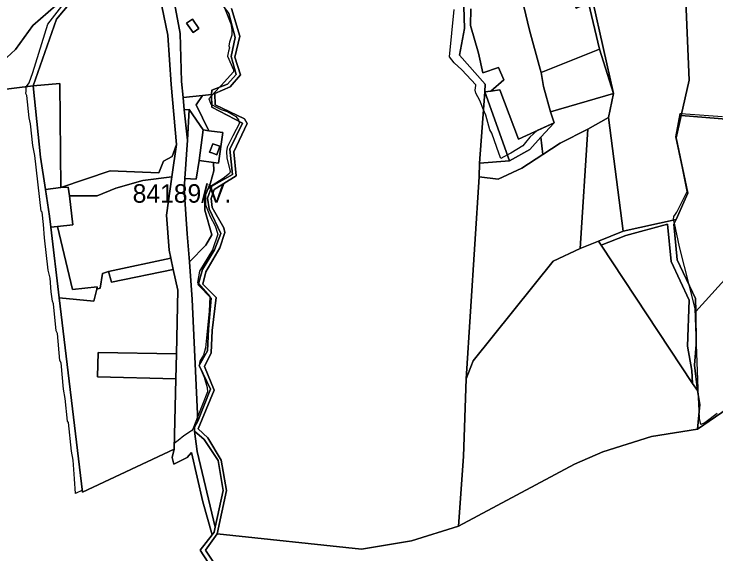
# Model space of a CAD drawing. Extents: x -477304 to -465429, y -1159113 to -1149210.
# Drawn here: x -473001 to -472430, y -1154555 to -1154116 of the extents above; entities that cross this region are included whole.
import ezdxf

# ---------------------------------------------------------------- set-up
doc = ezdxf.new("R2010")
doc.units = 0
for name, color, linetype in [('BPEJ_s', 7, 'Continuous'), ('ostatni_s', 7, 'Continuous'), ('PUPFL_s', 7, 'Continuous'), ('trav_porost_s', 7, 'Continuous'), ('voda_s', 7, 'Continuous')]:
    doc.layers.add(name, color=color, linetype=linetype)

msp = doc.modelspace()

# ---------------------------------------------------------------- linework, layer by layer
at = {"layer": 'BPEJ_s'}
for points in [[(-472987.65, -1154205.34), (-472988.93, -1154200.66), (-472990.63, -1154182.37), (-472991.48, -1154180.88), (-472991.4, -1154178.87), (-472991.26, -1154175.57), (-472991.11, -1154175.34), (-472991.05, -1154175.25), (-472988.93, -1154172.16), (-472985.95, -1154163.66), (-472973.62, -1154124.53), (-472956.73, -1154102.22)], [(-472991.48, -1154180.88), (-472991.4, -1154178.87), (-472991.26, -1154175.57), (-472991.11, -1154175.34), (-472991.05, -1154175.25), (-472988.93, -1154172.16), (-472985.95, -1154163.66), (-472973.62, -1154124.53), (-472956.73, -1154102.22)], [(-472530.52, -1154106.09), (-472513.63, -1154180.72), (-472525.05, -1154144.76), (-472572.62, -1154163.71), (-472570.69, -1154175.01), (-472564.9, -1154195.68), (-472562.1, -1154204.59), (-472575.93, -1154210.94), (-472581.73, -1154216.39), (-472585.21, -1154220.65), (-472587.46, -1154223.41), (-472597.25, -1154229.15), (-472600, -1154230.66), (-472605.31, -1154233.57), (-472606.6, -1154230), (-472612.77, -1154212.99), (-472614.26, -1154210.44), (-472617.66, -1154198.53), (-472619.46, -1154194.14), (-472622.55, -1154186.62), (-472625.74, -1154180.67), (-472626.17, -1154178.12), (-472625.78, -1154174.24), (-472625.74, -1154173.87), (-472637.01, -1154161.53), (-472643.39, -1154156), (-472647.22, -1154150.9), (-472643.18, -1154112.63)], [(-472530.52, -1154106.09), (-472513.63, -1154180.72), (-472525.05, -1154144.76), (-472572.62, -1154163.71), (-472570.69, -1154175.01), (-472564.9, -1154195.68), (-472562.1, -1154204.59), (-472575.93, -1154210.94), (-472581.73, -1154216.39), (-472585.21, -1154220.65), (-472587.46, -1154223.41), (-472597.25, -1154229.15), (-472600, -1154230.66), (-472605.31, -1154233.57), (-472606.6, -1154230), (-472612.77, -1154212.99), (-472614.26, -1154210.44), (-472617.66, -1154198.53), (-472619.46, -1154194.14), (-472622.55, -1154186.62), (-472625.74, -1154180.67), (-472626.17, -1154178.12), (-472625.78, -1154174.24), (-472625.74, -1154173.87), (-472637.01, -1154161.53), (-472643.39, -1154156), (-472647.22, -1154150.9), (-472643.18, -1154112.63)], [(-472829.93, -1154111.14), (-472824.98, -1154124.11), (-472824.13, -1154129.21), (-472824.13, -1154133.46), (-472826.05, -1154139.21), (-472826.47, -1154141.97), (-472826.05, -1154143.67), (-472826.67, -1154146.52), (-472827.53, -1154150.48), (-472822.64, -1154161.53), (-472822.64, -1154163.23), (-472832.85, -1154174.29), (-472834.08, -1154175.62), (-472840.6, -1154182.69), (-472842.8, -1154185.07), (-472841.14, -1154189.39), (-472840.48, -1154189.75), (-472836.49, -1154191.89), (-472832.85, -1154193.85), (-472827.75, -1154195.55), (-472820.94, -1154199.59), (-472818.6, -1154202.15), (-472818.31, -1154203.43), (-472818.18, -1154203.99), (-472817.96, -1154204.91), (-472823.14, -1154215.26), (-472827.75, -1154224.47), (-472828.39, -1154227.88), (-472828.17, -1154232.98), (-472825.41, -1154244.04), (-472826.05, -1154245.74), (-472831.15, -1154249.99), (-472842.21, -1154256.79), (-472843.39, -1154258.15), (-472843.69, -1154258.5), (-472844.61, -1154261.02), (-472845.4, -1154263.17), (-472845.61, -1154271.25), (-472841.78, -1154280.61), (-472837.53, -1154288.26), (-472835.4, -1154295.07), (-472839.87, -1154307.83), (-472850.5, -1154325.05), (-472852.1, -1154334.31), (-472851.6, -1154334.86), (-472851.27, -1154335.23), (-472841.99, -1154345.68), (-472842, -1154345.86), (-472842.42, -1154357.58), (-472845.4, -1154387.35), (-472847.1, -1154393.31), (-472848.39, -1154395.44), (-472850.07, -1154398.2), (-472850.71, -1154401.81), (-472846.46, -1154411.17), (-472844.12, -1154419.67), (-472843.91, -1154423.08), (-472851.96, -1154443.63), (-472855.82, -1154453.48), (-472856.88, -1154454.97), (-472863.05, -1154459.01), (-472867.79, -1154462.74), (-472870.94, -1154465.22), (-472871.05, -1154469.78), (-472945.41, -1154504.69), (-472945.61, -1154503.04), (-472951.09, -1154505.74), (-472951.93, -1154493.89), (-472952.99, -1154478.79), (-472954.48, -1154471.35), (-472956.82, -1154448.17), (-472957.67, -1154446.89), (-472959.58, -1154428.61), (-472961.07, -1154420.95), (-472962.98, -1154399.69), (-472963.83, -1154397.77), (-472965.96, -1154375.87), (-472966.81, -1154373.53), (-472969.15, -1154351.63), (-472970, -1154349.5), (-472971.07, -1154341.85), (-472971.92, -1154330.79), (-472973.4, -1154324.41), (-472976.28, -1154298.04), (-472977.34, -1154287.13), (-472978.3, -1154277.21), (-472978.93, -1154276.57), (-472979.14, -1154276.36), (-472984.25, -1154231.28), (-472985.95, -1154222.98), (-472987.65, -1154205.34), (-472988.93, -1154200.66), (-472990.63, -1154182.37), (-472991.48, -1154180.88)], [(-472829.93, -1154111.14), (-472824.98, -1154124.11), (-472824.13, -1154129.21), (-472824.13, -1154133.46), (-472826.05, -1154139.21), (-472826.47, -1154141.97), (-472826.05, -1154143.67), (-472826.67, -1154146.52), (-472827.53, -1154150.48), (-472822.64, -1154161.53), (-472822.64, -1154163.23), (-472832.85, -1154174.29), (-472834.08, -1154175.62), (-472840.6, -1154182.69), (-472842.8, -1154185.07), (-472841.14, -1154189.39), (-472840.48, -1154189.75), (-472836.49, -1154191.89), (-472832.85, -1154193.85), (-472827.75, -1154195.55), (-472820.94, -1154199.59), (-472818.6, -1154202.15), (-472818.31, -1154203.43), (-472818.18, -1154203.99), (-472817.96, -1154204.91), (-472823.14, -1154215.26), (-472827.75, -1154224.47), (-472828.39, -1154227.88), (-472828.17, -1154232.98), (-472825.41, -1154244.04), (-472826.05, -1154245.74), (-472831.15, -1154249.99), (-472842.21, -1154256.79), (-472843.39, -1154258.15), (-472843.69, -1154258.5), (-472844.61, -1154261.02), (-472845.4, -1154263.17), (-472845.61, -1154271.25), (-472841.78, -1154280.61), (-472837.53, -1154288.26), (-472835.4, -1154295.07), (-472839.87, -1154307.83), (-472850.5, -1154325.05), (-472852.1, -1154334.31), (-472851.6, -1154334.86), (-472851.27, -1154335.23), (-472841.99, -1154345.68), (-472842, -1154345.86), (-472842.42, -1154357.58), (-472845.4, -1154387.35), (-472847.1, -1154393.31), (-472848.39, -1154395.44), (-472850.07, -1154398.2), (-472850.71, -1154401.81), (-472846.46, -1154411.17), (-472844.12, -1154419.67), (-472843.91, -1154423.08), (-472851.96, -1154443.63), (-472855.82, -1154453.48), (-472856.88, -1154454.97), (-472863.05, -1154459.01), (-472867.79, -1154462.74), (-472870.94, -1154465.22), (-472871.05, -1154469.78), (-472945.41, -1154504.69), (-472945.61, -1154503.04), (-472951.09, -1154505.74), (-472951.93, -1154493.89), (-472952.99, -1154478.79), (-472954.48, -1154471.35), (-472956.82, -1154448.17), (-472957.67, -1154446.89), (-472959.58, -1154428.61), (-472961.07, -1154420.95), (-472962.98, -1154399.69), (-472963.83, -1154397.77), (-472965.96, -1154375.87), (-472966.81, -1154373.53), (-472969.15, -1154351.63), (-472970, -1154349.5), (-472971.07, -1154341.85), (-472971.92, -1154330.79), (-472973.4, -1154324.41), (-472976.28, -1154298.04), (-472977.34, -1154287.13), (-472978.3, -1154277.21), (-472978.93, -1154276.57), (-472979.14, -1154276.36), (-472984.25, -1154231.28), (-472985.95, -1154222.98), (-472987.65, -1154205.34)], [(-472429.42, -1154440.69), (-472439.62, -1154448.34), (-472442.81, -1154449.83), (-472443.87, -1154444.73), (-472444.11, -1154438.57), (-472444.52, -1154427.69), (-472446.71, -1154370.27), (-472447.27, -1154355.49), (-472451.91, -1154337.24), (-472460.02, -1154305.35), (-472464.25, -1154286.23), (-472464.85, -1154283.52), (-472464.91, -1154283.25), (-472464.69, -1154280.7), (-472463.36, -1154278.76), (-472462.36, -1154277.3), (-472453.86, -1154260.3), (-472457.75, -1154241.45), (-472462.99, -1154216.1), (-472459.67, -1154197.08), (-472458.48, -1154197.17), (-472455.13, -1154197.41), (-472425.17, -1154199.53)], [(-472462.99, -1154216.1), (-472459.67, -1154197.08), (-472458.48, -1154197.17), (-472455.13, -1154197.41), (-472425.17, -1154199.53)], [(-472429.42, -1154440.69), (-472439.62, -1154448.34), (-472442.81, -1154449.83), (-472443.87, -1154444.73), (-472444.11, -1154438.57), (-472444.52, -1154427.69), (-472446.71, -1154370.27), (-472447.27, -1154355.49), (-472451.91, -1154337.24), (-472460.02, -1154305.35), (-472464.25, -1154286.23), (-472464.85, -1154283.52), (-472464.91, -1154283.25), (-472464.69, -1154280.7), (-472463.36, -1154278.76), (-472462.36, -1154277.3), (-472453.86, -1154260.3), (-472457.75, -1154241.45), (-472462.99, -1154216.1)]]:
    msp.add_lwpolyline(points, dxfattribs=at)
at = {"layer": 'ostatni_s'}
for points in [[(-472849.47, -1154085.86), (-472826.39, -1154115.72), (-472821.44, -1154135.2), (-472824.75, -1154150.78), (-472820.69, -1154165.29), (-472827.68, -1154173.11), (-472840.4, -1154178.1), (-472840.62, -1154181.74), (-472847.97, -1154182.52), (-472863.75, -1154184.19), (-472865.04, -1154171.03), (-472866.09, -1154132.18), (-472873.67, -1154091.14), (-472874.54, -1154081.71), (-472850.45, -1154078.85)], [(-472860.87, -1154123.6), (-472856.13, -1154120.35), (-472850.9, -1154128.03), (-472855.64, -1154131.28)], [(-472860.87, -1154123.6), (-472855.64, -1154131.28), (-472850.9, -1154128.03), (-472856.13, -1154120.35)], [(-472979.68, -1154232.42), (-472985.59, -1154174.56), (-472964.05, -1154172.75), (-472963.19, -1154257.3), (-472975.68, -1154258.78)], [(-472842.76, -1154211.06), (-472847.39, -1154210.45), (-472858.83, -1154193.67), (-472862.79, -1154194.03), (-472863.75, -1154184.19), (-472847.97, -1154182.52), (-472853.07, -1154189.9)], [(-472838.2, -1154307.72), (-472847.95, -1154323.76), (-472851.53, -1154336.12), (-472840.79, -1154347.1), (-472843.18, -1154372.38), (-472843.81, -1154389.75), (-472850.55, -1154401.76), (-472841.36, -1154421.1), (-472851.81, -1154446.9), (-472856.2, -1154348.26), (-472858.61, -1154317.62), (-472845.2, -1154304.01), (-472840.29, -1154295.5), (-472846.14, -1154275.51), (-472845.97, -1154264.61), (-472841.48, -1154253.36), (-472838.81, -1154243.57), (-472839.1, -1154236.76), (-472834.84, -1154237.32), (-472831.53, -1154212.54), (-472842.76, -1154211.06), (-472853.07, -1154189.9), (-472847.97, -1154182.52), (-472840.62, -1154181.74), (-472840.44, -1154191.97), (-472815.32, -1154204.98), (-472825.67, -1154226.16), (-472823.67, -1154246.68), (-472840.44, -1154256.02), (-472843.81, -1154265.84), (-472842.41, -1154274.41), (-472833.08, -1154294.59)], [(-472862.79, -1154194.03), (-472858.83, -1154193.67), (-472860.13, -1154218.63)], [(-472847.39, -1154210.45), (-472850.7, -1154235.23), (-472853.06, -1154250.42), (-472862.35, -1154249.95), (-472860.13, -1154218.63), (-472858.83, -1154193.67)], [(-472839.1, -1154236.76), (-472850.7, -1154235.23), (-472847.39, -1154210.45), (-472842.76, -1154211.06), (-472831.53, -1154212.54), (-472834.84, -1154237.32)], [(-472841.4, -1154226.45), (-472839.66, -1154221.58), (-472833.9, -1154223.64), (-472836.36, -1154230.52), (-472839.55, -1154229.38), (-472842.12, -1154228.46)], [(-472839.55, -1154229.38), (-472836.36, -1154230.52), (-472833.9, -1154223.64), (-472839.66, -1154221.58), (-472841.4, -1154226.45), (-472842.12, -1154228.46)], [(-472862.35, -1154249.95), (-472853.06, -1154250.42), (-472850.7, -1154235.23), (-472839.1, -1154236.76), (-472838.81, -1154243.57), (-472841.48, -1154253.36), (-472845.97, -1154264.61), (-472846.14, -1154275.51), (-472840.29, -1154295.5), (-472845.2, -1154304.01), (-472858.61, -1154317.62), (-472860.41, -1154294.73), (-472862.93, -1154258.74)], [(-472953.65, -1154340), (-472933.45, -1154337.95), (-472933.87, -1154339.66), (-472936.3, -1154349.56), (-472964.39, -1154346.9), (-472971.3, -1154289.5), (-472965.81, -1154288.88)], [(-472924.26, -1154325.38), (-472873.71, -1154314.49), (-472871.67, -1154323.79), (-472921.9, -1154334.14)], [(-472932.86, -1154391.11), (-472869.16, -1154392.27), (-472869.66, -1154412.62), (-472933.18, -1154410.97)], [(-472852.18, -1154471.56), (-472854.38, -1154455.06), (-472846.45, -1154462), (-472835.17, -1154478.9), (-472831.05, -1154503.44), (-472837.52, -1154533.23)]]:
    msp.add_lwpolyline(points, close=True, dxfattribs=at)
msp.add_lwpolyline([(-472873.67, -1154091.14), (-472866.09, -1154132.18), (-472865.04, -1154171.03), (-472863.75, -1154184.19), (-472862.79, -1154194.03), (-472860.13, -1154218.63), (-472862.35, -1154249.95), (-472862.93, -1154258.74), (-472860.41, -1154294.73), (-472858.61, -1154317.62), (-472856.2, -1154348.26), (-472851.81, -1154446.9), (-472854.54, -1154451.8), (-472854.38, -1154455.06), (-472852.18, -1154471.56), (-472837.52, -1154533.23), (-472838.38, -1154537.19), (-472840.12, -1154539.39), (-472847.77, -1154512.55), (-472856.9, -1154472.41), (-472860.49, -1154476.63), (-472871.2, -1154481.8), (-472872.59, -1154476.5), (-472871.05, -1154469.78), (-472869.66, -1154412.62), (-472869.16, -1154392.27), (-472867.91, -1154340.66), (-472871.67, -1154323.79), (-472873.71, -1154314.49), (-472874.92, -1154308.19), (-472877.2, -1154279.68), (-472872.82, -1154248.6), (-472869.12, -1154222.34), (-472873.31, -1154173.48), (-472876.21, -1154133.46), (-472885.88, -1154086.14)], dxfattribs=at)
at = {"layer": 'PUPFL_s'}
for points in [[(-472458.42, -1153888.26), (-472456.78, -1153884.15), (-472439.98, -1153867.43), (-472437.22, -1153927.39), (-472440.92, -1153982.01), (-472446.75, -1154005.15), (-472458.38, -1154050.48), (-472455.38, -1154092.67), (-472452.22, -1154169.89), (-472458.83, -1154198.7), (-472462.78, -1154216.95), (-472453.33, -1154261.75), (-472462.8, -1154283.06), (-472506.01, -1154292.72), (-472517.7, -1154200.33), (-472513.63, -1154180.72), (-472530.52, -1154106.09), (-472468.28, -1154095.1), (-472465.12, -1154094.54), (-472465.12, -1154053.36), (-472458.54, -1153980.69)], [(-472394.38, -1154075.28), (-472401.16, -1154143.14), (-472408.66, -1154202.61), (-472458.83, -1154198.7), (-472452.22, -1154169.89), (-472455.38, -1154092.67)], [(-472939.6, -1154087.83), (-472966.52, -1154120.43), (-472985.59, -1154174.56), (-473014.5, -1154178.21), (-473015.58, -1154176.17), (-473017.49, -1154164.82), (-473010.66, -1154154.9), (-472999.88, -1154145.17), (-472985.98, -1154125.69), (-472967.29, -1154109.37), (-472954.27, -1154100.56), (-472943.73, -1154089.62), (-472939.03, -1154083), (-472934.33, -1154083.49)], [(-472570.69, -1154175.01), (-472572.62, -1154163.71), (-472525.05, -1154144.76), (-472513.63, -1154180.72), (-472564.9, -1154195.68)], [(-472598.3, -1154235.42), (-472622.78, -1154237.39), (-472618.34, -1154179.49)], [(-472618.34, -1154179.49), (-472613.45, -1154178.87), (-472606.1, -1154177.93), (-472591.09, -1154217.9), (-472562.1, -1154204.59), (-472572.95, -1154216.31), (-472581.78, -1154226.42), (-472598.3, -1154235.42)], [(-472571.18, -1154230.49), (-472572.95, -1154216.31), (-472562.1, -1154204.59), (-472564.9, -1154195.68), (-472513.63, -1154180.72), (-472517.7, -1154200.33), (-472534.54, -1154209.69), (-472557.09, -1154221.24)], [(-472453.33, -1154261.75), (-472462.78, -1154216.95), (-472458.83, -1154198.7), (-472408.66, -1154202.61), (-472420.83, -1154329.2), (-472446.86, -1154358.02), (-472447.19, -1154347.21), (-472462.02, -1154315.9), (-472464.6, -1154287), (-472462.8, -1154283.06)], [(-472534.54, -1154209.69), (-472517.7, -1154200.33), (-472506.01, -1154292.72), (-472525.94, -1154300.77), (-472540.75, -1154306.65)], [(-472588.19, -1154241.54), (-472571.18, -1154230.49), (-472557.09, -1154221.24), (-472534.54, -1154209.69), (-472540.75, -1154306.65), (-472562.68, -1154317.09), (-472627.92, -1154398.05), (-472633.5, -1154412.68), (-472623.07, -1154248.49), (-472607.42, -1154250.34)], [(-472598.3, -1154235.42), (-472581.78, -1154226.42), (-472572.95, -1154216.31), (-472571.18, -1154230.49), (-472588.19, -1154241.54), (-472607.42, -1154250.34), (-472623.07, -1154248.49), (-472622.78, -1154237.39)], [(-472953.28, -1154287.48), (-472965.81, -1154288.88), (-472971.3, -1154289.5), (-472972.38, -1154280.5), (-472975.68, -1154258.78), (-472963.19, -1154257.3), (-472957.17, -1154256.98), (-472956.15, -1154263.81)], [(-472445.38, -1154422.01), (-472447.92, -1154401.59), (-472446.53, -1154384.74), (-472446.86, -1154358.02), (-472420.83, -1154329.2), (-472360.26, -1154262.14), (-472384.09, -1154410.55), (-472401.42, -1154423.45), (-472445.42, -1154453.37), (-472443.65, -1154433.44)], [(-472445.38, -1154422.01), (-472449.51, -1154416.38), (-472449.98, -1154405.9), (-472453.63, -1154386.05), (-472452.36, -1154348.77), (-472466.94, -1154317.29), (-472469.9, -1154286.92), (-472503.75, -1154296.21), (-472523.88, -1154304.06), (-472525.94, -1154300.77), (-472506.01, -1154292.72), (-472462.8, -1154283.06), (-472464.6, -1154287), (-472462.02, -1154315.9), (-472447.19, -1154347.21), (-472446.86, -1154358.02), (-472446.53, -1154384.74), (-472447.92, -1154401.59)], [(-472469.9, -1154286.92), (-472466.94, -1154317.29), (-472452.36, -1154348.77), (-472453.63, -1154386.05), (-472449.98, -1154405.9), (-472449.51, -1154416.38), (-472523.88, -1154304.06), (-472503.75, -1154296.21)], [(-472525.94, -1154300.77), (-472523.88, -1154304.06), (-472449.51, -1154416.38), (-472445.38, -1154422.01), (-472443.65, -1154433.44), (-472445.42, -1154453.37), (-472482.74, -1154459.45), (-472522.51, -1154471.95), (-472545.51, -1154481.81), (-472639.66, -1154532.36), (-472635.69, -1154475.83), (-472633.5, -1154412.68), (-472627.92, -1154398.05), (-472562.68, -1154317.09), (-472540.75, -1154306.65)]]:
    msp.add_lwpolyline(points, close=True, dxfattribs=at)
for points in [[(-473028.58, -1154013.8), (-472995.53, -1153992.99), (-472988.79, -1153987.76), (-472984.49, -1154008.11), (-472964.26, -1154022.87), (-472935.97, -1154028.45), (-472913.88, -1154035), (-472888.58, -1154036.61), (-472885.69, -1154043.9), (-472884.83, -1154050.9), (-472898.18, -1154053.7), (-472922.79, -1154060.6), (-472939.03, -1154083), (-472943.73, -1154089.62), (-472954.27, -1154100.56), (-472967.29, -1154109.37), (-472985.98, -1154125.69), (-472999.88, -1154145.17), (-473010.66, -1154154.9)], [(-472635.34, -1154110.22), (-472635.02, -1154127.99), (-472638.86, -1154149.74), (-472618.01, -1154173.32), (-472618.34, -1154179.49), (-472622.78, -1154237.39), (-472623.07, -1154248.49), (-472633.5, -1154412.68), (-472635.69, -1154475.83), (-472639.66, -1154532.36), (-472678.01, -1154544.18), (-472718.68, -1154550.96), (-472836.02, -1154538.48), (-472828.3, -1154503.34), (-472832.72, -1154478.74), (-472843.67, -1154460.59), (-472851.46, -1154453.29), (-472838.41, -1154421.8), (-472846.27, -1154402.6), (-472840.76, -1154391.42), (-472840.13, -1154373.22), (-472836.79, -1154346.46), (-472847.74, -1154335.73), (-472845.21, -1154325.68), (-472833.81, -1154306.11), (-472829.81, -1154293.73), (-472830.58, -1154290.05), (-472840.13, -1154273.36), (-472840.79, -1154266.21), (-472838.34, -1154258.74), (-472820.51, -1154247.63), (-472822.37, -1154228.2), (-472811.6, -1154205.15), (-472813.85, -1154201.26), (-472837.5, -1154189.94), (-472837.81, -1154180.81), (-472825.5, -1154175.49), (-472817.11, -1154165.54), (-472821.53, -1154151.22), (-472817.57, -1154134.23), (-472824.3, -1154111.78)], [(-473014.5, -1154178.21), (-472985.59, -1154174.56), (-472979.68, -1154232.42), (-472975.68, -1154258.78), (-472972.38, -1154280.5), (-472971.3, -1154289.5), (-472964.39, -1154346.9), (-472945.41, -1154504.69), (-472871.05, -1154469.78), (-472872.59, -1154476.5), (-472871.2, -1154481.8), (-472860.49, -1154476.63), (-472856.9, -1154472.41), (-472847.77, -1154512.55), (-472840.12, -1154539.39), (-472849.91, -1154551.76), (-472833.75, -1154576.35)], [(-472829.82, -1154575.42), (-472845.56, -1154551.84), (-472836.02, -1154538.48), (-472718.68, -1154550.96), (-472678.01, -1154544.18), (-472639.66, -1154532.36), (-472545.51, -1154481.81), (-472522.51, -1154471.95), (-472482.74, -1154459.45), (-472445.42, -1154453.37), (-472401.42, -1154423.45), (-472384.09, -1154410.55), (-472379.28, -1154406.61), (-472329.41, -1154411.16), (-472150.64, -1154427.27), (-472018.16, -1154439.35), (-472022.72, -1154458.3), (-471976.15, -1154460.64), (-471961.55, -1154462.05), (-471926.3, -1154475.13), (-471912.68, -1154523.9), (-471906.1, -1154578.81)]]:
    msp.add_lwpolyline(points, dxfattribs=at)
at = {"layer": 'trav_porost_s'}
for points in [[(-472609.2, -1153970.72), (-472587.7, -1153958.11), (-472599.42, -1153927.91), (-472542.68, -1153905.09), (-472536.32, -1153934.3), (-472532.33, -1153972.86), (-472547.08, -1154060.89), (-472541.57, -1154078.78), (-472537.98, -1154103.11), (-472545.36, -1154106.84), (-472544.23, -1154111.56), (-472534.13, -1154107.04), (-472525.05, -1154144.76), (-472572.62, -1154163.71), (-472573.26, -1154160.94), (-472582.03, -1154129.27), (-472589.55, -1154097.38), (-472596.73, -1154062.16), (-472603.59, -1154006.47), (-472609.63, -1153975.68)], [(-472538.77, -1153903.52), (-472532.25, -1153931.35), (-472528.59, -1153971.02), (-472538.45, -1154060.94), (-472530.52, -1154106.09), (-472513.63, -1154180.72), (-472525.05, -1154144.76), (-472534.13, -1154107.04), (-472544.23, -1154111.56), (-472545.36, -1154106.84), (-472537.98, -1154103.11), (-472541.57, -1154078.78), (-472547.08, -1154060.89), (-472532.33, -1153972.86), (-472536.32, -1153934.3), (-472542.68, -1153905.09)], [(-472966.52, -1154120.43), (-472939.6, -1154087.83), (-472934.33, -1154083.49), (-472898.18, -1154053.7), (-472885.88, -1154086.14), (-472876.21, -1154133.46), (-472873.31, -1154173.48), (-472869.12, -1154222.34), (-472872.72, -1154232.12), (-472879.7, -1154235.67), (-472883.35, -1154245.37), (-472923.11, -1154243.52), (-472963.19, -1154257.3), (-472964.05, -1154172.75), (-472985.59, -1154174.56)], [(-472879.7, -1154235.67), (-472872.72, -1154232.12), (-472869.12, -1154222.34), (-472872.82, -1154248.6), (-472896.57, -1154251.42), (-472918.33, -1154257.71), (-472933.69, -1154264.02), (-472956.15, -1154263.81), (-472957.17, -1154256.98), (-472963.19, -1154257.3), (-472923.11, -1154243.52), (-472883.35, -1154245.37)], [(-472953.28, -1154287.48), (-472956.15, -1154263.81), (-472933.69, -1154264.02), (-472918.33, -1154257.71), (-472896.57, -1154251.42), (-472872.82, -1154248.6), (-472877.2, -1154279.68), (-472874.92, -1154308.19), (-472873.71, -1154314.49), (-472924.26, -1154325.38), (-472929.15, -1154327.02), (-472931.2, -1154338.95), (-472933.87, -1154339.66), (-472933.45, -1154337.95), (-472953.65, -1154340), (-472965.81, -1154288.88)], [(-472929.15, -1154327.02), (-472924.26, -1154325.38), (-472921.9, -1154334.14), (-472871.67, -1154323.79), (-472867.91, -1154340.66), (-472869.16, -1154392.27), (-472932.86, -1154391.11), (-472933.18, -1154410.97), (-472869.66, -1154412.62), (-472871.05, -1154469.78), (-472945.41, -1154504.69), (-472964.39, -1154346.9), (-472936.3, -1154349.56), (-472933.87, -1154339.66), (-472931.2, -1154338.95)]]:
    msp.add_lwpolyline(points, close=True, dxfattribs=at)
for points in [[(-472589.55, -1154097.38), (-472582.03, -1154129.27), (-472573.26, -1154160.94), (-472572.62, -1154163.71), (-472570.69, -1154175.01), (-472564.9, -1154195.68), (-472562.1, -1154204.59), (-472591.09, -1154217.9), (-472606.1, -1154177.93), (-472613.45, -1154178.87), (-472603.04, -1154169.65), (-472607.33, -1154159.62), (-472619.87, -1154164.04), (-472623.58, -1154148.09), (-472630.14, -1154125.46), (-472629.76, -1154112.03)], [(-472629.76, -1154112.03), (-472630.14, -1154125.46), (-472623.58, -1154148.09), (-472619.87, -1154164.04), (-472607.33, -1154159.62), (-472603.04, -1154169.65), (-472613.45, -1154178.87), (-472618.34, -1154179.49), (-472618.01, -1154173.32), (-472638.86, -1154149.74), (-472635.02, -1154127.99), (-472635.34, -1154110.22)]]:
    msp.add_lwpolyline(points, dxfattribs=at)
at = {"layer": 'voda_s'}
for points in [[(-472824.3, -1154111.78), (-472817.57, -1154134.23), (-472821.53, -1154151.22), (-472817.11, -1154165.54), (-472825.5, -1154175.49), (-472837.81, -1154180.81), (-472837.5, -1154189.94), (-472813.85, -1154201.26), (-472811.6, -1154205.15), (-472822.37, -1154228.2), (-472820.51, -1154247.63), (-472838.34, -1154258.74), (-472840.79, -1154266.21), (-472840.13, -1154273.36), (-472830.58, -1154290.05), (-472829.81, -1154293.73), (-472833.81, -1154306.11), (-472845.21, -1154325.68), (-472847.74, -1154335.73), (-472836.79, -1154346.46), (-472840.13, -1154373.22), (-472840.76, -1154391.42), (-472846.27, -1154402.6), (-472838.41, -1154421.8), (-472851.46, -1154453.29), (-472843.67, -1154460.59), (-472832.72, -1154478.74), (-472828.3, -1154503.34), (-472836.02, -1154538.48), (-472845.56, -1154551.84), (-472829.82, -1154575.42)], [(-472851.81, -1154446.9), (-472841.36, -1154421.1), (-472850.55, -1154401.76), (-472843.81, -1154389.75), (-472843.18, -1154372.38), (-472840.79, -1154347.1), (-472851.53, -1154336.12), (-472847.95, -1154323.76), (-472838.2, -1154307.72), (-472833.08, -1154294.59), (-472842.41, -1154274.41), (-472843.81, -1154265.84), (-472840.44, -1154256.02), (-472823.67, -1154246.68), (-472825.67, -1154226.16), (-472815.32, -1154204.98), (-472840.44, -1154191.97), (-472840.62, -1154181.74), (-472840.4, -1154178.1), (-472827.68, -1154173.11), (-472820.69, -1154165.29), (-472824.75, -1154150.78), (-472821.44, -1154135.2), (-472826.39, -1154115.72)], [(-472801.98, -1154920.79), (-472802.39, -1154887.45), (-472815.87, -1154831.12), (-472823.05, -1154807.58), (-472833, -1154722.2), (-472842.6, -1154672.34), (-472846.89, -1154627.94), (-472835.17, -1154611.5), (-472833.75, -1154576.35), (-472849.91, -1154551.76), (-472840.12, -1154539.39), (-472838.38, -1154537.19), (-472837.52, -1154533.23), (-472831.05, -1154503.44), (-472835.17, -1154478.9), (-472846.45, -1154462), (-472854.38, -1154455.06), (-472854.54, -1154451.8), (-472851.81, -1154446.9)]]:
    msp.add_lwpolyline(points, dxfattribs=at)

# ---------------------------------------------------------------- texts
at = {"layer": 'BPEJ_s'}
msp.add_text('84189/V.', height=15, dxfattribs=at).set_placement((-472904.72, -1154269.51))

doc.saveas('drawing.dxf')
